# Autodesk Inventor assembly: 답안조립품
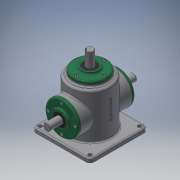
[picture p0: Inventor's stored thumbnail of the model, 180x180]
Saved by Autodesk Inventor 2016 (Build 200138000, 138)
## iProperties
Created: 2019-08
Part Number: 답안조립품
Material: 일반
Document SubType Name: Assembly
Designer: user
Author: user
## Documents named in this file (16)
- D:\490823V1002\답안조립품.iam
- D:\490823V1002\메인 베벨기어.ipt
- D:\490823V1002\메인 축.ipt
- 메인 축.ipt
- D:\490823V1002\베어링 6203.ipt
- D:\490823V1002\본체.ipt
- D:\490823V1002\볼트 M4.ipt
- 볼트 M4.ipt
- D:\490823V1002\서브 베벨기어.ipt
- D:\490823V1002\서브 축.ipt
- 서브 축.ipt
- D:\490823V1002\오일 실.ipt
- 오일 실.ipt
- D:\490823V1002\커버.ipt
- D:\490823V1002\키 4x4.ipt
- D:\490823V1002\키 5x5.ipt
